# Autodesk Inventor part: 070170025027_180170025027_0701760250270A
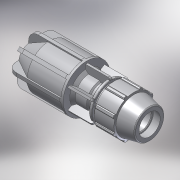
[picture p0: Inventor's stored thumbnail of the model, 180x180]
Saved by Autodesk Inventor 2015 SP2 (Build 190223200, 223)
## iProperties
Created: 2017-02
Part Number: 070170025027_180170025027_0701760250270A
Material: PVC-Piping
Description: PLASSON PLASS4 COUPLING 20-27*25
Document SubType Name: Modeling
Designer: KIM
Mass: 92.6774 g
Surface Area: 199.44 cm^2
Volume: 66.1981 cm^3
Density: 1.4 g/cm^3
Appearance: Smooth - White
Author: KIM
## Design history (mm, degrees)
derived "070170.ipt"
feature "Solid1::070170.ipt"
tag "TaggingFeature1"
body "Solid1"
other parameters: "d2" = 25, "d4" = 12.14286, "d5" = 20.3, "d7" = 54, "d8" = 32.54092, "d9" = 11.57143, "d11" = 4.25, "d12" = 43.2, "d13" = 120 deg, "d14" = 37.5, "d15" = 12 deg, "d16" = 48.6, "d18" = 1.25, "d19" = 35 deg, "d20" = 17.5 deg, "d21" = 50.22, "d23" = 0, "d25" = 360 deg, "d27" = 1.08, "d42" = 26.1, "d43" = 1.62, "d46" = 0.75, "d53" = 0.5, "d67" = 2.7, "d70" = 22.5, "d71" = 58, "d74" = 180 deg, "d75" = 27, "d76" = 71, "d80" = 22.5, "d84" = 67.45, "d85" = 135 deg, "d86" = 3.55, "d89" = 3.55, "d90" = 135 deg, "d94" = 3.55, "d97" = 4.32, "d98" = 0, "d100" = 360 deg, "d102" = 78.1, "d103" = 14.2, "d104" = 5.68, "d105" = 0, "d110" = 85, "d112" = 102, "d113" = 28.9, "d114" = 68, "d115" = 42.6, "d116" = 102, "d117" = 4.25, "d118" = 27, "d119" = 2.7, "d120" = 0, "d121" = 2.7, "d123" = 360 deg, "d_" = 25, "E_" = 54, "A_" = 81, "l_" = 58, "d_1" = 27, "E_1" = 71, "l_1" = 85, "d106" = 32.54092
